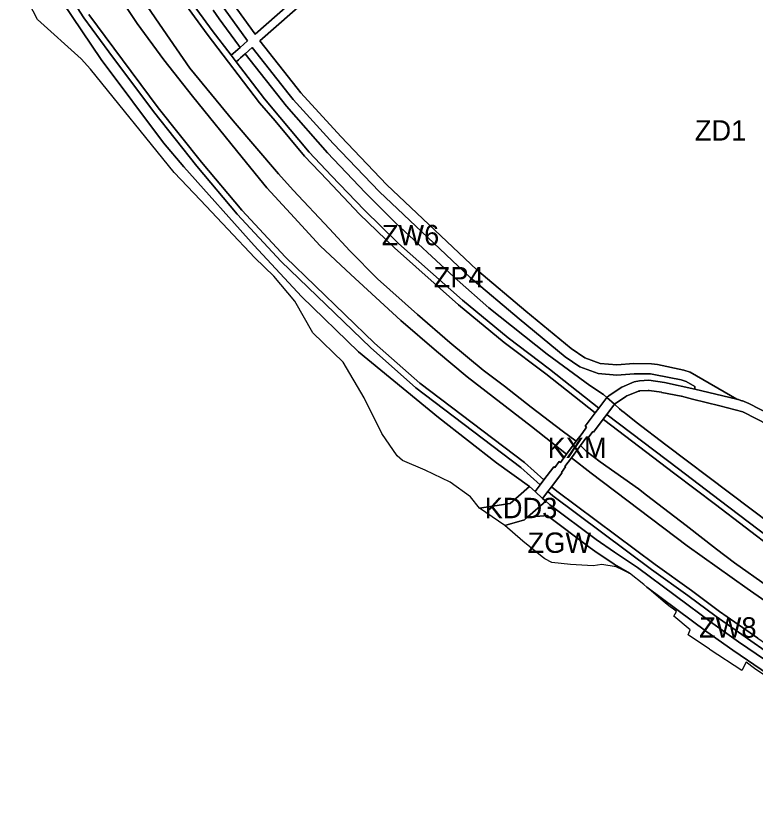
# Model space of a CAD drawing. Extents: x -297419 to -295590, y 31782 to 32981.
# Drawn here: x -296742.3 to -296379.3, y 31815.1 to 32210.2 of the extents above; entities that cross this region are included whole.
import ezdxf

# ---------------------------------------------------------------- set-up
doc = ezdxf.new("R2010")
doc.units = 0
doc.layers.add('linie_rozgraniczajace', color=7, linetype='Continuous')
doc.layers.add('oznaczenia_przeznaczen', color=7, linetype='Continuous')

msp = doc.modelspace()

# ---------------------------------------------------------------- linework, layer by layer
at = {"layer": 'linie_rozgraniczajace'}
for points in [[(-296636.097, 32216.799), (-296617.9, 32232.78), (-296577.49, 32268.15), (-296574.16, 32273.74), (-296563.4, 32291.74), (-296550.24, 32315.54), (-296539.01, 32335.5), (-296531.55, 32348.39), (-296521.27, 32366.92), (-296506.9, 32357.447), (-296530.986, 32313.692), (-296554.264, 32273.86), (-296566.047, 32253.693), (-296566.937, 32252.512), (-296624.981, 32201.389)], [(-296629.881, 32191.744), (-296626.389, 32194.819), (-296608.337, 32171.681), (-296606.334, 32169.326), (-296586.68, 32147.733), (-296563.978, 32123.894), (-296519.472, 32081.939), (-296495.365, 32061.552), (-296472.859, 32042.989), (-296465.6, 32037.965), (-296456.704, 32034.706), (-296447.434, 32033.996), (-296439.01, 32034.629), (-296430.94, 32034.573), (-296428.508, 32034.188), (-296415.889, 32031.626), (-296413.447, 32030.783), (-296409.268, 32028.339), (-296409.268, 32027.099), (-296424.11, 32030.356), (-296431.877, 32031.429), (-296436.429, 32031.195), (-296439.078, 32030.612), (-296445.128, 32028.003), (-296451.343, 32024.017), (-296452.456, 32023.058), (-296453.991, 32024.446), (-296460.81, 32028.84), (-296481.68, 32044.21), (-296510.36, 32066.99), (-296525.843, 32080.7), (-296527.258, 32082.044), (-296555.98, 32108.5), (-296570.95, 32123.62), (-296589.51, 32143.17), (-296609.67, 32165.96)], [(-296634.371, 32187.789), (-296633.249, 32188.778), (-296632.126, 32189.766), (-296631.003, 32190.755), (-296629.881, 32191.744), (-296609.67, 32165.96), (-296589.51, 32143.17), (-296570.95, 32123.62), (-296555.98, 32108.5), (-296527.258, 32082.044), (-296525.843, 32080.7), (-296510.36, 32066.99), (-296481.68, 32044.21), (-296460.81, 32028.84), (-296453.991, 32024.446), (-296452.456, 32023.058), (-296456.384, 32017.798), (-296480.484, 32036.953), (-296500.908, 32052.3), (-296523.174, 32070.738), (-296554.624, 32098.612), (-296571.58, 32115.059), (-296587.489, 32131.843), (-296598.506, 32143.467), (-296612.909, 32160.688), (-296620.459, 32169.598)], [(-296487.622, 31976.847), (-296485.095, 31980.149), (-296483.267, 31982.539), (-296478.387, 31988.918), (-296477.99, 31988.631), (-296475.826, 31991.557), (-296475.175, 31991.075), (-296472.124, 31995.202), (-296467.449, 32001.524), (-296464.589, 32005.392), (-296462.382, 32008.45), (-296463.033, 32008.893), (-296458.179, 32015.393), (-296456.384, 32017.798), (-296452.456, 32023.058), (-296448.73, 32019.691), (-296452.468, 32014.685), (-296454.263, 32012.28), (-296458.978, 32005.966), (-296459.325, 32006.242), (-296461.532, 32003.185), (-296462.218, 32003.689), (-296465.314, 31999.479), (-296469.797, 31993.383), (-296472.968, 31989.07), (-296472.717, 31988.885), (-296474.702, 31986.2), (-296474.364, 31985.943), (-296474.46, 31985.823), (-296479.527, 31979.199), (-296481.355, 31976.809), (-296483.907, 31973.474)], [(-296514.92, 31968.58), (-296499.87, 31970.99), (-296490.331, 31979.308), (-296487.622, 31976.847), (-296483.907, 31973.474), (-296482.325, 31972.038), (-296491.302, 31964.212), (-296492.887, 31962.991), (-296502.4, 31960.18)], [(-296481.355, 31976.809), (-296479.527, 31979.199), (-296477.014, 31976.955), (-296428.719, 31940.953), (-296410.828, 31928.184), (-296397.047, 31917.948), (-296378.375, 31904.878), (-296352.032, 31886.438), (-296317.549, 31862.949), (-296272.656, 31832.66), (-296265.083, 31827.167), (-296249.478, 31815.846), (-296253.776, 31815.117), (-296257.672, 31817.283), (-296257.249, 31817.777), (-296266.844, 31824.738), (-296274.376, 31830.202), (-296319.232, 31860.466), (-296353.737, 31883.969), (-296380.095, 31902.42), (-296398.802, 31915.514), (-296412.594, 31925.758), (-296430.487, 31938.529), (-296478.913, 31974.629)], [(-296483.907, 31973.474), (-296481.355, 31976.809), (-296478.913, 31974.629), (-296430.487, 31938.529), (-296412.594, 31925.758), (-296398.802, 31915.514), (-296380.095, 31902.42), (-296353.737, 31883.969), (-296319.232, 31860.466), (-296274.376, 31830.202), (-296266.844, 31824.738), (-296257.249, 31817.777), (-296257.672, 31817.283), (-296266.222, 31822.036), (-296274.92, 31826.85), (-296338.924, 31869.776), (-296387.76, 31903.103), (-296400.462, 31911.98), (-296437.41, 31939.52), (-296448.701, 31947.107), (-296457.633, 31953.293), (-296480.39, 31970.28), (-296482.325, 31972.038)], [(-296502.4, 31960.18), (-296492.887, 31962.991), (-296491.302, 31964.212), (-296483.266, 31964.94), (-296481.64, 31964.974), (-296460.564, 31949.242), (-296458.223, 31947.6), (-296448.875, 31941.23), (-296448.865, 31941.223), (-296448.747, 31941.146), (-296448.627, 31941.071), (-296441.29, 31936.68), (-296447.85, 31939.79), (-296454.896, 31941.035), (-296459.1, 31940.28), (-296470.17, 31941.02), (-296479.41, 31942.04), (-296482.83, 31943.73), (-296484.12, 31944.718), (-296493.64, 31952.46)]]:
    msp.add_lwpolyline(points, close=True, dxfattribs=at)
for points in [[(-296703.71, 32252.679), (-296670.068, 32203.65), (-296657.01, 32184.618), (-296635.714, 32158.758), (-296613.508, 32132.754), (-296606.272, 32124.819), (-296588.433, 32105.76), (-296578.514, 32094.963), (-296564.984, 32081.238), (-296545.308, 32063.708), (-296529.437, 32049.951), (-296513.029, 32036.438), (-296502.687, 32028.6), (-296489.535, 32018.29), (-296474.262, 32006.696), (-296467.449, 32001.524), (-296472.124, 31995.202), (-296489.454, 32008.75), (-296520.933, 32033.123), (-296536.03, 32045.751), (-296553.578, 32060.792), (-296578.02, 32083.403), (-296593.085, 32097.516), (-296607.6, 32113.272), (-296619.31, 32125.987), (-296631.364, 32140.872), (-296655.706, 32170.928), (-296669.744, 32188.827), (-296682.955, 32206.55), (-296716.319, 32257.025)], [(-296716.319, 32257.025), (-296682.955, 32206.55), (-296669.744, 32188.827), (-296655.706, 32170.928), (-296631.364, 32140.872), (-296619.31, 32125.987), (-296607.6, 32113.272), (-296593.085, 32097.516), (-296578.02, 32083.403), (-296553.578, 32060.792), (-296536.03, 32045.751), (-296520.933, 32033.123), (-296489.454, 32008.75), (-296472.124, 31995.202), (-296475.175, 31991.075), (-296475.826, 31991.557), (-296477.99, 31988.631), (-296478.387, 31988.918), (-296483.267, 31982.539), (-296492.746, 31991.004), (-296544.188, 32030.079), (-296566.36, 32049.69), (-296610.042, 32091.859), (-296631.612, 32115.004), (-296651.315, 32138.524), (-296672.536, 32165.159), (-296694.342, 32194.502), (-296706.643, 32211.054)], [(-296668.036, 32228.272), (-296648.571, 32201.417), (-296622.796, 32167.716), (-296615.204, 32158.756), (-296600.748, 32141.471), (-296589.666, 32129.779), (-296573.714, 32112.949), (-296556.664, 32096.412), (-296525.126, 32068.459), (-296502.767, 32049.945), (-296482.319, 32034.579), (-296458.179, 32015.393), (-296463.033, 32008.893), (-296462.382, 32008.45), (-296464.589, 32005.392), (-296467.449, 32001.524), (-296474.262, 32006.696), (-296489.535, 32018.29), (-296502.687, 32028.6), (-296513.029, 32036.438), (-296529.437, 32049.951), (-296545.308, 32063.708), (-296564.984, 32081.238), (-296578.514, 32094.963), (-296588.433, 32105.76), (-296606.272, 32124.819), (-296613.508, 32132.754), (-296635.714, 32158.758), (-296657.01, 32184.618), (-296670.068, 32203.65), (-296703.71, 32252.679)], [(-296563.988, 32249.779), (-296622.63, 32198.13), (-296604.46, 32174.84), (-296602.58, 32172.63), (-296583.02, 32151.14), (-296560.45, 32127.44), (-296516.14, 32085.67), (-296492.16, 32065.39), (-296469.84, 32046.98), (-296463.28, 32042.44), (-296455.633, 32039.639), (-296447.43, 32039.01), (-296439.18, 32039.63), (-296430.53, 32039.57), (-296427.62, 32039.11), (-296414.57, 32036.46), (-296411.47, 32035.39), (-296388.692, 32022.207), (-296409.268, 32027.099), (-296409.268, 32028.339), (-296413.447, 32030.783), (-296415.889, 32031.626), (-296428.508, 32034.188), (-296430.94, 32034.573), (-296439.01, 32034.629), (-296447.434, 32033.996), (-296456.704, 32034.706), (-296465.6, 32037.965), (-296472.859, 32042.989), (-296495.365, 32061.552), (-296519.472, 32081.939), (-296563.978, 32123.894), (-296586.68, 32147.733), (-296606.334, 32169.326), (-296608.337, 32171.681), (-296626.389, 32194.819), (-296629.881, 32191.744), (-296631.003, 32190.755), (-296632.126, 32189.766), (-296633.249, 32188.778), (-296634.371, 32187.789), (-296636.807, 32190.974), (-296635.72, 32191.931), (-296634.598, 32192.92), (-296633.475, 32193.908), (-296632.352, 32194.897), (-296628.751, 32198.069), (-296640.249, 32214.007)], [(-296636.097, 32216.799), (-296624.981, 32201.389), (-296566.937, 32252.512)], [(-296370.916, 32013.982), (-296383.112, 32020.217), (-296383.493, 32020.376), (-296383.876, 32020.533), (-296384.26, 32020.687), (-296384.646, 32020.838), (-296385.034, 32020.985), (-296385.423, 32021.13), (-296385.814, 32021.272), (-296386.207, 32021.411), (-296386.601, 32021.546), (-296386.997, 32021.679), (-296387.394, 32021.808), (-296387.793, 32021.934), (-296388.193, 32022.058), (-296388.594, 32022.178), (-296388.692, 32022.207), (-296411.47, 32035.39), (-296414.57, 32036.46), (-296427.62, 32039.11), (-296430.53, 32039.57), (-296439.18, 32039.63), (-296447.43, 32039.01), (-296455.633, 32039.639), (-296463.28, 32042.44), (-296469.84, 32046.98), (-296492.16, 32065.39), (-296516.14, 32085.67), (-296560.45, 32127.44), (-296583.02, 32151.14), (-296602.58, 32172.63), (-296604.46, 32174.84), (-296622.63, 32198.13), (-296563.988, 32249.779)], [(-296733.238, 32247.109), (-296709.114, 32209.35), (-296696.75, 32192.712), (-296674.914, 32163.329), (-296653.639, 32136.625), (-296633.861, 32113.017), (-296612.183, 32089.756), (-296568.396, 32047.486), (-296546.092, 32027.758), (-296494.656, 31988.687), (-296485.095, 31980.149), (-296487.622, 31976.847), (-296490.331, 31979.308), (-296490.4, 31979.37), (-296506.52, 31990.87), (-296535.04, 32013.21), (-296574.21, 32045.44), (-296602.207, 32072.556), (-296625.49, 32097.56), (-296660.06, 32136.23), (-296669.9, 32148.04), (-296700.61, 32188.99), (-296719.6, 32217.08)], [(-296706.643, 32211.054), (-296694.342, 32194.502), (-296672.536, 32165.159), (-296651.315, 32138.524), (-296631.612, 32115.004), (-296610.042, 32091.859), (-296566.36, 32049.69), (-296544.188, 32030.079), (-296492.746, 31991.004), (-296483.267, 31982.539), (-296485.095, 31980.149), (-296494.656, 31988.687), (-296546.092, 32027.758), (-296568.396, 32047.486), (-296612.183, 32089.756), (-296633.861, 32113.017), (-296653.639, 32136.625), (-296674.914, 32163.329), (-296696.75, 32192.712), (-296709.114, 32209.35), (-296733.238, 32247.109)], [(-296665.589, 32230.008), (-296646.165, 32203.209), (-296636.807, 32190.974), (-296634.371, 32187.789), (-296620.459, 32169.598), (-296612.909, 32160.688), (-296598.506, 32143.467), (-296587.489, 32131.843), (-296571.58, 32115.059), (-296554.624, 32098.612), (-296523.174, 32070.738), (-296500.908, 32052.3), (-296480.484, 32036.953), (-296456.384, 32017.798), (-296458.179, 32015.393), (-296482.319, 32034.579), (-296502.767, 32049.945), (-296525.126, 32068.459), (-296556.664, 32096.412), (-296573.714, 32112.949), (-296589.666, 32129.779), (-296600.748, 32141.471), (-296615.204, 32158.756), (-296622.796, 32167.716), (-296648.571, 32201.417), (-296668.036, 32228.272)], [(-296645.682, 32213.119), (-296642.579, 32208.932), (-296633.207, 32195.987), (-296632.352, 32194.897), (-296633.475, 32193.908), (-296634.598, 32192.92), (-296635.72, 32191.931), (-296636.807, 32190.974), (-296646.165, 32203.209), (-296665.589, 32230.008)], [(-296719.6, 32217.08), (-296700.61, 32188.99), (-296669.9, 32148.04), (-296660.06, 32136.23), (-296625.49, 32097.56), (-296602.207, 32072.556), (-296574.21, 32045.44), (-296535.04, 32013.21), (-296506.52, 31990.87), (-296490.4, 31979.37), (-296490.331, 31979.308), (-296499.87, 31970.99), (-296514.92, 31968.58), (-296519.37, 31974.24), (-296529.23, 31981.41), (-296541.56, 31987.37), (-296552.68, 31992.08), (-296555.26, 31994.33), (-296562.77, 32005.33), (-296571.51, 32022.76), (-296581.82, 32040.31), (-296596.77, 32054.77), (-296605.51, 32070.27), (-296615.85, 32082.61), (-296625.15, 32091.63), (-296638.38, 32105.59), (-296651.88, 32119.84), (-296664.76, 32133.44), (-296705.88, 32184.25), (-296710.44, 32189.3), (-296731.83, 32208.6), (-296742.31, 32228.86)], [(-296640.249, 32214.007), (-296628.751, 32198.069), (-296632.352, 32194.897), (-296633.207, 32195.987), (-296642.579, 32208.932), (-296645.682, 32213.119)], [(-296373.192, 32009.53), (-296385.388, 32015.765), (-296385.478, 32015.808), (-296385.57, 32015.848), (-296385.663, 32015.885), (-296385.695, 32015.896), (-296396.89, 32018.861), (-296396.895, 32018.862), (-296410.425, 32022.235), (-296415.694, 32023.567), (-296415.765, 32023.588), (-296415.871, 32023.615), (-296415.978, 32023.638), (-296425.487, 32025.508), (-296425.544, 32025.518), (-296425.652, 32025.535), (-296431.59, 32026.362), (-296431.596, 32026.363), (-296431.705, 32026.376), (-296431.814, 32026.385), (-296431.923, 32026.39), (-296432.033, 32026.391), (-296432.142, 32026.388), (-296436.198, 32026.201), (-296436.234, 32026.199), (-296436.344, 32026.19), (-296436.452, 32026.178), (-296436.561, 32026.162), (-296436.668, 32026.141), (-296436.775, 32026.117), (-296436.881, 32026.089), (-296436.986, 32026.057), (-296437.089, 32026.021), (-296437.192, 32025.982), (-296442.622, 32023.77), (-296442.681, 32023.745), (-296442.78, 32023.7), (-296442.878, 32023.651), (-296442.974, 32023.598), (-296443.069, 32023.542), (-296443.161, 32023.483), (-296448.73, 32019.691), (-296452.456, 32023.058), (-296451.343, 32024.017), (-296445.128, 32028.003), (-296439.078, 32030.612), (-296436.429, 32031.195), (-296431.877, 32031.429), (-296424.11, 32030.356), (-296409.268, 32027.099), (-296388.692, 32022.207), (-296388.594, 32022.178), (-296388.193, 32022.058), (-296387.793, 32021.934), (-296387.394, 32021.808), (-296386.997, 32021.679), (-296386.601, 32021.546), (-296386.207, 32021.411), (-296385.814, 32021.272), (-296385.423, 32021.13), (-296385.034, 32020.985), (-296384.646, 32020.838), (-296384.26, 32020.687), (-296383.876, 32020.533), (-296383.493, 32020.376), (-296383.112, 32020.217), (-296370.916, 32013.982)], [(-296360.98, 31952.542), (-296423.474, 31999.716), (-296437.942, 32010.912), (-296443.086, 32014.942), (-296443.858, 32015.585), (-296444.973, 32016.429), (-296446.25, 32017.45), (-296448.73, 32019.691), (-296443.161, 32023.483), (-296443.069, 32023.542), (-296442.974, 32023.598), (-296442.878, 32023.651), (-296442.78, 32023.7), (-296442.681, 32023.745), (-296442.622, 32023.77), (-296437.192, 32025.982), (-296437.089, 32026.021), (-296436.986, 32026.057), (-296436.881, 32026.089), (-296436.775, 32026.117), (-296436.668, 32026.141), (-296436.561, 32026.162), (-296436.452, 32026.178), (-296436.344, 32026.19), (-296436.234, 32026.199), (-296436.198, 32026.201), (-296432.142, 32026.388), (-296432.033, 32026.391), (-296431.923, 32026.39), (-296431.814, 32026.385), (-296431.705, 32026.376), (-296431.596, 32026.363), (-296431.59, 32026.362), (-296425.652, 32025.535), (-296425.544, 32025.518), (-296425.487, 32025.508), (-296415.978, 32023.638), (-296415.871, 32023.615), (-296415.765, 32023.588), (-296415.694, 32023.567), (-296410.425, 32022.235), (-296396.895, 32018.862), (-296396.89, 32018.861), (-296385.695, 32015.896), (-296385.663, 32015.885), (-296385.57, 32015.848), (-296385.478, 32015.808), (-296385.388, 32015.765), (-296373.192, 32009.53)], [(-296368.229, 31950.676), (-296397.342, 31972.794), (-296417.237, 31987.91), (-296452.204, 32014.476), (-296452.468, 32014.685), (-296448.73, 32019.691), (-296446.25, 32017.45), (-296444.973, 32016.429), (-296443.858, 32015.585), (-296443.086, 32014.942), (-296437.942, 32010.912), (-296423.474, 31999.716), (-296360.98, 31952.542)], [(-296369.982, 31948.24), (-296399.156, 31970.405), (-296419.052, 31985.521), (-296454.045, 32012.107), (-296454.263, 32012.28), (-296452.468, 32014.685), (-296452.204, 32014.476), (-296417.237, 31987.91), (-296397.342, 31972.794), (-296368.229, 31950.676)], [(-296373.63, 31930.291), (-296389.702, 31941.812), (-296398.597, 31948.545), (-296413.557, 31960.123), (-296432.873, 31975.071), (-296436.882, 31978.174), (-296455.756, 31991.442), (-296462.475, 31996.652), (-296465.314, 31999.479), (-296462.218, 32003.689), (-296461.532, 32003.185), (-296459.325, 32006.242), (-296458.978, 32005.966), (-296454.263, 32012.28), (-296454.045, 32012.107), (-296419.052, 31985.521), (-296399.156, 31970.405), (-296369.982, 31948.24)], [(-296353.694, 31908.355), (-296383.559, 31929.188), (-296413.008, 31950.12), (-296460.08, 31985.786), (-296469.788, 31993.376), (-296469.797, 31993.383), (-296465.314, 31999.479), (-296462.475, 31996.652), (-296455.756, 31991.442), (-296436.882, 31978.174), (-296432.873, 31975.071), (-296413.557, 31960.123), (-296398.597, 31948.545), (-296389.702, 31941.812), (-296373.63, 31930.291)], [(-296378.375, 31904.878), (-296397.047, 31917.948), (-296410.828, 31928.184), (-296428.719, 31940.953), (-296477.014, 31976.955), (-296479.527, 31979.199), (-296474.46, 31985.823), (-296474.364, 31985.943), (-296474.702, 31986.2), (-296472.717, 31988.885), (-296472.968, 31989.07), (-296469.797, 31993.383), (-296469.788, 31993.376), (-296460.08, 31985.786), (-296413.008, 31950.12), (-296383.559, 31929.188), (-296353.694, 31908.355)], [(-296341.725, 31865.635), (-296390.602, 31898.989), (-296403.389, 31907.926), (-296432.746, 31929.808), (-296434.26, 31931.1), (-296441.29, 31936.68), (-296448.627, 31941.071), (-296448.747, 31941.146), (-296448.865, 31941.223), (-296448.875, 31941.23), (-296458.223, 31947.6), (-296460.564, 31949.242), (-296481.64, 31964.974), (-296483.266, 31964.94), (-296491.302, 31964.212), (-296482.325, 31972.038), (-296480.39, 31970.28), (-296457.633, 31953.293), (-296448.701, 31947.107), (-296437.41, 31939.52), (-296400.462, 31911.98), (-296387.76, 31903.103), (-296338.924, 31869.776)], [(-296373.41, 31885.58), (-296379.96, 31889.93), (-296383.99, 31893.05), (-296386.09, 31889), (-296401.73, 31899.07), (-296402.02, 31899.478), (-296412.44, 31906.49), (-296411.44, 31908.888), (-296419.51, 31915.59), (-296418.17, 31917.94), (-296419.72, 31919.15), (-296421.39, 31920.28), (-296423.67, 31922.06), (-296432.746, 31929.808), (-296403.389, 31907.926), (-296390.602, 31898.989), (-296341.725, 31865.635)]]:
    msp.add_lwpolyline(points, dxfattribs=at)

# ---------------------------------------------------------------- texts
at = {"layer": 'oznaczenia_przeznaczen'}
for s, p in [('ZD1', (-296409.237015, 32149.110001)), ('ZW6', (-296562.894806, 32097.724001)), ('ZP4', (-296537.404832, 32077.044001)), ('KXM', (-296481.470394, 31993.317001)), ('KDD3', (-296512.373745, 31963.730001)), ('ZGW', (-296491.2828, 31946.705001)), ('ZW8', (-296407.179961, 31905.09693))]:
    msp.add_text(s, height=10, dxfattribs=at).set_placement(p)

doc.saveas('drawing.dxf')
